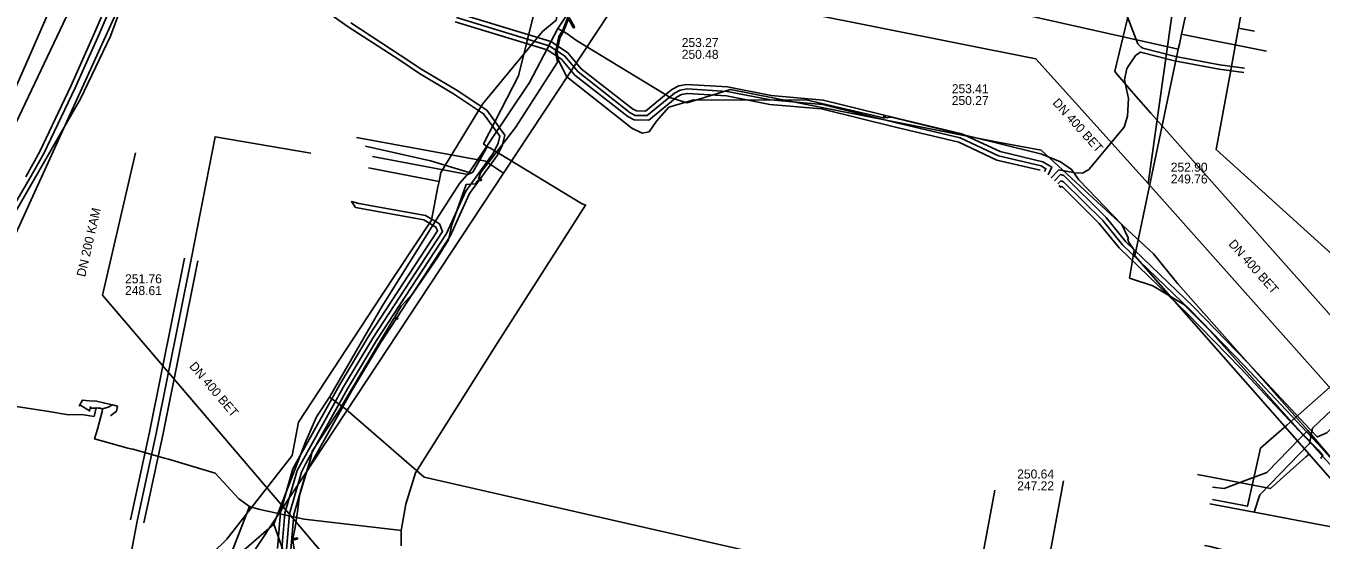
# Model space of a CAD drawing. Extents: x -598233 to -596890, y -1157848 to -1156431.
# Drawn here: x -597184.3 to -597069.1, y -1157535.5 to -1157489.7 of the extents above; entities that cross this region are included whole.
import ezdxf

# ---------------------------------------------------------------- set-up
doc = ezdxf.new("R2010")
doc.units = 0
for name, color, linetype in [('Vrstva 12', 7, 'Continuous'), ('Vrstva 13', 7, 'Continuous'), ('Vrstva 16', 7, 'Continuous'), ('Vrstva 19', 7, 'Continuous'), ('Vrstva 37', 7, 'Continuous'), ('Vrstva 38', 7, 'Continuous'), ('Vrstva 42', 7, 'Continuous'), ('Vrstva 48', 7, 'Continuous'), ('Vrstva 51', 7, 'Continuous'), ('Vrstva 55', 7, 'Continuous'), ('Vrstva 58', 7, 'Continuous'), ('Vrstva 9', 7, 'Continuous')]:
    doc.layers.add(name, color=color, linetype=linetype)

msp = doc.modelspace()

# ---------------------------------------------------------------- linework, layer by layer
at = {"layer": 'Vrstva 12'}
for points in [[(-597138.34, -1157490.22), (-597137.14, -1157489.22), (-597136.59, -1157486.27), (-597125.79, -1157469.77), (-597124.28, -1157461.93), (-597123.72, -1157458.99), (-597123.41, -1157457.42)], [(-597174.83, -1157472), (-597177.82, -1157478.71), (-597180.61, -1157484.62), (-597183.79, -1157492), (-597187.73, -1157500.85), (-597191.49, -1157508.74), (-597195.12, -1157516.56)], [(-597076.44, -1157489.91), (-597076.05, -1157487.75), (-597077.34, -1157487.41)], [(-597140.9, -1157493.31), (-597138.34, -1157490.22)], [(-597054.42, -1157516.11), (-597061.64, -1157514.31), (-597064.06, -1157513.71), (-597078.43, -1157500.72), (-597077.19, -1157493.99), (-597076.47, -1157490.05), (-597076.44, -1157489.91)], [(-597076.44, -1157489.91), (-597075.01, -1157490.19)], [(-597147.55, -1157503.56), (-597147.39, -1157502.77), (-597143.68, -1157496.67), (-597140.9, -1157493.31)], [(-597153.84, -1157502.35), (-597147.55, -1157503.56)], [(-597167.72, -1157536.67), (-597166.44, -1157535.4), (-597160.63, -1157527.93), (-597160.06, -1157524.98), (-597152.69, -1157513.78), (-597148.22, -1157507), (-597147.65, -1157504.05), (-597147.55, -1157503.56)], [(-597074.55, -1157531.45), (-597070.12, -1157526.89), (-597069.86, -1157525.52), (-597063.07, -1157519.07), (-597053.69, -1157520.64)], [(-597075.04, -1157532.98), (-597074.55, -1157531.45)], [(-597078.98, -1157532.23), (-597075.04, -1157532.98)], [(-597052.3, -1157558.29), (-597051.14, -1157552.4), (-597050.78, -1157550.53), (-597059.55, -1157540.67), (-597063.92, -1157539.81), (-597063.78, -1157539.1), (-597063.22, -1157536.13), (-597063.05, -1157535.26), (-597075.04, -1157532.98)]]:
    msp.add_lwpolyline(points, dxfattribs=at)
at = {"layer": 'Vrstva 13'}
for p, q in [((-597187.26, -1157502.69), (-597170.45, -1157467.35)), ((-597081.79, -1157491.79), (-597081.7, -1157491.34)), ((-597082.19, -1157491.7), (-597081.79, -1157491.79)), ((-597081.85, -1157492.09), (-597081.79, -1157491.79))]:
    msp.add_line(p, q, dxfattribs=at)
for points in [[(-597026.92, -1157402.38), (-597036.5, -1157429.51), (-597036.81, -1157430.39), (-597055.35, -1157434.11), (-597061.26, -1157454.58), (-597076.71, -1157468.49), (-597081.5, -1157490.45), (-597081.7, -1157491.34)], [(-597082.19, -1157491.7), (-597108.02, -1157485.89), (-597126.01, -1157481.84), (-597126.61, -1157481.7), (-597127.71, -1157481.44), (-597141.82, -1157502.82), (-597164.3, -1157536.89), (-597164.29, -1157537.06), (-597161.57, -1157540.12), (-597158.67, -1157543.36), (-597141.32, -1157562.83), (-597138.68, -1157565.79), (-597117.79, -1157589.22), (-597114.74, -1157592.65), (-597094.8, -1157615.01), (-597091.36, -1157618.87), (-597086.95, -1157623.82), (-597081.9, -1157629.49), (-597080.86, -1157631.56)], [(-597081.5, -1157490.45), (-597081.25, -1157490.51), (-597073.95, -1157491.98)], [(-597010.06, -1157596.34), (-597010.19, -1157596.08), (-597019.57, -1157585.41), (-597022.72, -1157581.82), (-597034.39, -1157568.53), (-597043.31, -1157558.37), (-597046.79, -1157554.42), (-597066.65, -1157531.82), (-597070.16, -1157527.82), (-597081.02, -1157515.45), (-597085.67, -1157510.17), (-597081.85, -1157492.09)], [(-597141.82, -1157502.82), (-597142.26, -1157502.53), (-597143.41, -1157501.75), (-597154.9, -1157499.65)], [(-597070.16, -1157527.82), (-597070.44, -1157528.07), (-597073.59, -1157530.89), (-597080.09, -1157529.62)]]:
    msp.add_lwpolyline(points, dxfattribs=at)
at = {"layer": 'Vrstva 16'}
for points in [[(-597180.5, -1157524.34), (-597182.25, -1157524.03), (-597191.3, -1157522.62)], [(-597178.98, -1157524.36), (-597179.36, -1157524.3), (-597180.5, -1157524.34)], [(-597178.61, -1157524.42), (-597178.98, -1157524.36)], [(-597177.48, -1157523.8), (-597178.06, -1157523.69), (-597178.06, -1157523.7), (-597178.23, -1157524.47), (-597178.61, -1157524.42)]]:
    msp.add_lwpolyline(points, dxfattribs=at)
at = {"layer": 'Vrstva 19'}
for points in [[(-597065.1, -1157519.01), (-597084.25, -1157497.49), (-597085.78, -1157495.74), (-597087.36, -1157493.91), (-597087.44, -1157493.75), (-597085.94, -1157487.46)], [(-597138.99, -1157488.18), (-597140.48, -1157494.15), (-597143.59, -1157500.22), (-597143.27, -1157500.47), (-597143.03, -1157500.58), (-597134.88, -1157505.53), (-597134.52, -1157505.66), (-597142.35, -1157517.93), (-597149.65, -1157529.49), (-597150.51, -1157532.26), (-597150.93, -1157534.62), (-597150.91, -1157535.99)], [(-597143.27, -1157500.47), (-597144.54, -1157502.74), (-597144.99, -1157502.94), (-597153.48, -1157501.33)], [(-597065.1, -1157519.01), (-597065.32, -1157519.21), (-597072.13, -1157525.25), (-597074.47, -1157527.29), (-597075.65, -1157532.46), (-597078.75, -1157531.87)], [(-597175.22, -1157527.28), (-597178.19, -1157526.47), (-597177.93, -1157525.61), (-597177.53, -1157524.02)], [(-597177.53, -1157524.02), (-597177.48, -1157523.81), (-597177.48, -1157523.8)], [(-597171.62, -1157528.27), (-597171.97, -1157528.17), (-597174.8, -1157527.39), (-597174.98, -1157527.35), (-597175.22, -1157527.28)], [(-597150.93, -1157534.62), (-597151.13, -1157534.6), (-597159.56, -1157533.62), (-597163.62, -1157532.73), (-597164.42, -1157532.47), (-597165.37, -1157531.79), (-597167.48, -1157529.52), (-597171.62, -1157528.27)], [(-597164.42, -1157532.47), (-597167.64, -1157540.78), (-597168.21, -1157541.47), (-597169.13, -1157541.58), (-597173.47, -1157540.61)]]:
    msp.add_lwpolyline(points, dxfattribs=at)
at = {"layer": 'Vrstva 37'}
for points in [[(-597169.61, -1157510.5), (-597167.47, -1157499.58), (-597158.97, -1157501.05)], [(-597174.4, -1157533.8), (-597172.71, -1157526), (-597169.61, -1157510.5)], [(-597174.4, -1157533.8), (-597172.71, -1157526), (-597169.61, -1157510.5)], [(-597080.84, -1157542.09), (-597093.7, -1157539.3), (-597092.01, -1157530.19)], [(-597175.7, -1157550.96), (-597177.54, -1157550.44), (-597174.4, -1157533.8)]]:
    msp.add_lwpolyline(points, dxfattribs=at)
at = {"layer": 'Vrstva 38'}
for points in [[(-597174.99, -1157533.67), (-597173.3, -1157525.88), (-597170.2, -1157510.38)], [(-597173.82, -1157533.93), (-597172.12, -1157526.13), (-597169.02, -1157510.61)]]:
    msp.add_lwpolyline(points, dxfattribs=at)
at = {"layer": 'Vrstva 42'}
for points in [[(-597075.9, -1157493.47), (-597078.1, -1157493.18), (-597082.03, -1157492.44), (-597084.96, -1157491.69), (-597085.12, -1157491.58), (-597085.4, -1157491.33), (-597086.74, -1157487.85), (-597087.83, -1157485.44), (-597089.6, -1157483.06), (-597090.83, -1157481.21), (-597092.97, -1157478.52), (-597094.33, -1157477.55), (-597094.92, -1157477.28), (-597100.87, -1157476.16), (-597101.47, -1157475.86), (-597101.92, -1157475.33), (-597102, -1157474.66), (-597101.59, -1157471.8), (-597100.58, -1157467.66), (-597100.41, -1157467.46), (-597100.25, -1157467.42), (-597099.1, -1157467.34)], [(-597184.32, -1157503.14), (-597183.06, -1157500.9), (-597180.29, -1157495.08), (-597178.16, -1157490.29), (-597176.06, -1157485.39), (-597175.44, -1157484.62), (-597174.5, -1157482.84), (-597173.45, -1157481.76), (-597172.48, -1157481.55), (-597172.44, -1157481.51), (-597172.32, -1157481.38), (-597172.32, -1157481.34), (-597172.29, -1157481.22), (-597172.25, -1157481.04), (-597172.01, -1157480.58), (-597171.8, -1157480.17), (-597171.51, -1157479.62), (-597170.57, -1157477.79), (-597168.92, -1157473.93), (-597167.58, -1157470.87), (-597166.63, -1157470.7), (-597164.29, -1157470.3)], [(-597175.72, -1157485.59), (-597177.79, -1157490.45), (-597179.93, -1157495.24), (-597182.7, -1157501.08), (-597183.98, -1157503.34), (-597185.69, -1157506.27)], [(-597161.07, -1157538.33), (-597161.02, -1157538.28), (-597161.24, -1157537.24), (-597161.13, -1157536.31), (-597160.86, -1157533.13), (-597159.8, -1157529.44), (-597159.39, -1157528.67), (-597155.7, -1157522.02), (-597153.11, -1157517.72), (-597146.88, -1157508.2), (-597145.18, -1157504.42), (-597142.71, -1157501.01), (-597142.29, -1157500.16), (-597142.13, -1157499.52), (-597143.59, -1157497.53), (-597146.26, -1157495.76), (-597149.29, -1157493.95), (-597151.14, -1157492.71), (-597155.64, -1157489.79), (-597161.37, -1157485.75)], [(-597146.01, -1157488.97), (-597137.77, -1157491.49), (-597136.39, -1157492.39), (-597135.19, -1157493.82), (-597130.55, -1157497.45), (-597130.1, -1157497.68), (-597129.04, -1157497.7), (-597126.6, -1157495.71), (-597126.1, -1157495.44), (-597125.48, -1157495.33), (-597121.93, -1157495.55), (-597118.08, -1157496.3), (-597113.45, -1157496.72), (-597106.85, -1157498.34), (-597101.19, -1157499.69), (-597097.78, -1157501.28), (-597093.99, -1157502.18), (-597093.57, -1157502.43), (-597093.68, -1157502.67)], [(-597145.9, -1157488.59), (-597137.6, -1157491.12), (-597136.12, -1157492.09), (-597134.91, -1157493.53), (-597130.34, -1157497.11), (-597130, -1157497.28), (-597129.18, -1157497.3), (-597126.83, -1157495.37), (-597126.23, -1157495.05), (-597125.5, -1157494.93), (-597121.88, -1157495.15), (-597118.02, -1157495.91), (-597113.38, -1157496.32), (-597106.75, -1157497.95), (-597101.06, -1157499.31), (-597097.65, -1157500.9), (-597093.83, -1157501.81), (-597093.05, -1157502.28), (-597093.38, -1157502.96)], [(-597155.41, -1157489.46), (-597150.92, -1157492.38), (-597149.07, -1157493.61), (-597146.04, -1157495.42), (-597143.31, -1157497.23), (-597141.69, -1157499.44), (-597141.92, -1157500.3), (-597142.36, -1157501.21), (-597144.84, -1157504.63), (-597146.55, -1157508.42), (-597152.77, -1157517.93), (-597155.35, -1157522.22), (-597159.04, -1157528.86), (-597159.43, -1157529.59), (-597160.47, -1157533.2), (-597160.73, -1157536.34), (-597160.83, -1157537.22), (-597160.63, -1157538.18), (-597160.96, -1157538.45)], [(-597146.13, -1157489.36), (-597137.94, -1157491.85), (-597136.66, -1157492.69), (-597135.47, -1157494.11), (-597130.77, -1157497.79), (-597130.2, -1157498.07), (-597128.9, -1157498.1), (-597126.38, -1157496.04), (-597125.97, -1157495.82), (-597125.46, -1157495.73), (-597121.98, -1157495.95), (-597118.13, -1157496.7), (-597113.52, -1157497.11), (-597106.94, -1157498.73), (-597101.32, -1157500.07), (-597097.92, -1157501.66), (-597094.09, -1157502.57)], [(-597075.97, -1157493.86), (-597078.16, -1157493.58), (-597082.12, -1157492.83), (-597085.15, -1157492.05), (-597085.57, -1157492.32), (-597086.02, -1157492.97), (-597086.37, -1157493.51), (-597086.57, -1157494.52), (-597086.23, -1157496.17), (-597086.3, -1157497.76), (-597086.62, -1157498.73), (-597089.76, -1157502.49), (-597090.3, -1157502.81), (-597091, -1157502.8), (-597092.43, -1157502.54), (-597093.09, -1157503.24)], [(-597169.61, -1157510.5), (-597167.47, -1157499.58), (-597158.97, -1157501.05)], [(-597092.81, -1157503.51), (-597092.28, -1157502.95), (-597091.97, -1157503.04), (-597088.22, -1157506.77), (-597086.47, -1157508.93), (-597080.43, -1157514.73), (-597075.65, -1157519.66), (-597070.05, -1157525.64), (-597069.43, -1157526.28), (-597069.42, -1157526.27), (-597068.58, -1157525.94), (-597065.97, -1157523.31), (-597063.23, -1157519.67), (-597063.11, -1157519.59), (-597061.99, -1157519.05), (-597061.24, -1157518.5), (-597060.06, -1157518.59), (-597055.56, -1157519.31), (-597051.82, -1157519.78), (-597051.83, -1157519.88)], [(-597092.52, -1157503.78), (-597092.25, -1157503.51), (-597091.99, -1157503.58), (-597088.52, -1157507.04), (-597086.76, -1157509.2), (-597080.71, -1157515.02), (-597075.94, -1157519.93), (-597070.34, -1157525.91), (-597069.38, -1157526.9), (-597069.33, -1157526.96), (-597065.28, -1157531.47)], [(-597092.42, -1157503.92), (-597092.25, -1157504.08), (-597092.19, -1157504.02), (-597092.09, -1157504.05), (-597088.82, -1157507.31), (-597087.06, -1157509.47), (-597080.99, -1157515.3), (-597076.23, -1157520.21), (-597070.63, -1157526.19), (-597069.72, -1157527.13), (-597069.7, -1157527.16), (-597065.58, -1157531.74), (-597059.49, -1157538.54), (-597057.65, -1157540.65), (-597057.61, -1157540.79), (-597057.81, -1157541.11), (-597057.96, -1157541.17), (-597062.88, -1157539.95), (-597069, -1157538.52), (-597076.17, -1157536.79), (-597078.97, -1157536.05), (-597079.45, -1157535.96)], [(-597161.93, -1157536.23), (-597161.65, -1157532.98), (-597160.55, -1157529.13), (-597160.09, -1157528.28), (-597156.39, -1157521.62), (-597153.79, -1157517.3), (-597147.68, -1157507.96), (-597147.83, -1157507.62), (-597148.91, -1157506.98), (-597154.97, -1157505.87), (-597155.33, -1157505.35), (-597154.7, -1157505.52), (-597148.76, -1157506.6), (-597147.52, -1157507.34), (-597147.23, -1157508), (-597153.45, -1157517.51), (-597156.04, -1157521.82), (-597159.74, -1157528.48), (-597160.18, -1157529.29), (-597161.26, -1157533.06), (-597161.53, -1157536.27)], [(-597174.4, -1157533.8), (-597172.71, -1157526), (-597169.61, -1157510.5)], [(-597080.84, -1157542.09), (-597093.7, -1157539.3), (-597092.01, -1157530.19)], [(-597175.7, -1157550.96), (-597177.54, -1157550.44), (-597174.4, -1157533.8)]]:
    msp.add_lwpolyline(points, dxfattribs=at)
at = {"layer": 'Vrstva 48'}
for points in [[(-597176.78, -1157524.4), (-597176.25, -1157524), (-597176.16, -1157523.56), (-597176.61, -1157523.45), (-597177.28, -1157523.29), (-597178.01, -1157523.12), (-597178.67, -1157523.07), (-597179.28, -1157523.01), (-597179.5, -1157523.43), (-597179.57, -1157523.54)], [(-597179.5, -1157523.43), (-597178.63, -1157523.98), (-597178.58, -1157523.73), (-597178.56, -1157523.58)], [(-597176.61, -1157523.45), (-597176.99, -1157523.64), (-597177.48, -1157523.8), (-597177.8, -1157523.69), (-597178.02, -1157523.74), (-597178.58, -1157523.73)]]:
    msp.add_lwpolyline(points, dxfattribs=at)
at = {"layer": 'Vrstva 51'}
msp.add_lwpolyline([(-597162.16, -1157462.41), (-597162.37, -1157462.79), (-597162.45, -1157462.93), (-597162.55, -1157463.11), (-597162.62, -1157463.25), (-597162.74, -1157463.48), (-597162.94, -1157463.85), (-597163.14, -1157464.22), (-597163.47, -1157464.84), (-597163.79, -1157465.42), (-597165.74, -1157469.04), (-597165.98, -1157469.49), (-597166.19, -1157469.89), (-597166.4, -1157470.28), (-597166.63, -1157470.7), (-597171.49, -1157479.73), (-597171.77, -1157480.25), (-597171.97, -1157480.63), (-597172.29, -1157481.22), (-597172.34, -1157481.32), (-597172.44, -1157481.51), (-597172.71, -1157482.01), (-597176.29, -1157488.66), (-597185.93, -1157509.83)], dxfattribs=at)
at = {"layer": 'Vrstva 55'}
for points in [[(-597158.82, -1157477.15), (-597161.21, -1157476.69), (-597167.17, -1157475.31), (-597170.24, -1157474.33), (-597170.61, -1157474.61), (-597170.79, -1157475.8), (-597170.6, -1157477.17), (-597172.39, -1157481.32), (-597172.9, -1157482.22), (-597174.85, -1157485.44), (-597174.81, -1157485.58), (-597174.95, -1157485.61), (-597176.78, -1157490.63), (-597179.45, -1157496.2), (-597186.75, -1157508.85), (-597186.82, -1157508.91), (-597186.81, -1157508.98), (-597188.5, -1157512.52), (-597188.32, -1157512.99), (-597187.84, -1157513.32), (-597187.8, -1157513.39)], [(-597135.85, -1157488.35), (-597136.58, -1157490.15), (-597136.9, -1157490.67), (-597137.19, -1157492.05), (-597137.01, -1157492.94), (-597140.74, -1157498.77), (-597143.87, -1157502.79), (-597144.04, -1157503.35), (-597143.79, -1157503.37), (-597143.75, -1157503.43), (-597143.81, -1157503.49), (-597144.1, -1157503.47), (-597144.3, -1157503.76), (-597145.13, -1157503.83), (-597146.41, -1157507.43), (-597146.71, -1157508.76), (-597147.62, -1157510.24), (-597149.87, -1157513.54), (-597150.92, -1157514.67), (-597151.47, -1157515.6), (-597151.25, -1157515.69), (-597151.23, -1157515.77), (-597151.3, -1157515.8), (-597151.53, -1157515.7), (-597152.63, -1157517.54), (-597156.47, -1157523.98), (-597158.85, -1157527.57), (-597158.95, -1157528.16), (-597159.97, -1157531.49), (-597160.12, -1157532.71), (-597160.36, -1157534.34), (-597160.56, -1157535.35), (-597160.19, -1157535.27), (-597160.12, -1157535.32), (-597160.17, -1157535.39), (-597160.56, -1157535.47), (-597160.08, -1157538.81)], [(-597069.09, -1157528.2), (-597069.09, -1157528.11), (-597068.95, -1157527.95), (-597069.35, -1157527.45), (-597070.91, -1157525.84), (-597078.99, -1157516.83), (-597081.31, -1157514.5), (-597084.06, -1157512.85), (-597086.12, -1157512.16), (-597085.73, -1157509.67), (-597086.23, -1157508.92), (-597086.24, -1157508.79), (-597086.29, -1157508.73), (-597086.24, -1157508.67), (-597086.25, -1157508.57), (-597086.83, -1157507.4), (-597090.64, -1157503.42), (-597091.29, -1157502.49), (-597092.28, -1157501.82), (-597093.93, -1157501.12), (-597098.11, -1157500.1), (-597107.31, -1157497.83), (-597107.91, -1157497.9), (-597107.88, -1157497.76), (-597107.93, -1157497.69), (-597108, -1157497.74), (-597108.03, -1157497.9), (-597114.77, -1157496.33), (-597124.9, -1157496.3), (-597127.11, -1157496.96), (-597128.21, -1157498.19), (-597128.87, -1157499.14), (-597129.49, -1157499.27), (-597130.39, -1157498.81), (-597136.17, -1157494.26), (-597136.9, -1157492.86), (-597137.07, -1157492.05), (-597136.78, -1157490.71), (-597136.48, -1157490.21), (-597136.03, -1157489.1), (-597135.61, -1157489.86), (-597135.52, -1157489.9), (-597135.51, -1157489.8), (-597135.97, -1157488.96)]]:
    msp.add_lwpolyline(points, dxfattribs=at)
at = {"layer": 'Vrstva 58'}
for points in [[(-597120.35, -1157456.05), (-597120.83, -1157457.84), (-597120.99, -1157458.55), (-597121.21, -1157459.32), (-597122.25, -1157463.07), (-597125.24, -1157470.21), (-597132.81, -1157479.65), (-597135.11, -1157485.05), (-597135.84, -1157488.1), (-597136.26, -1157488.87), (-597136.97, -1157489.96)], [(-597136.97, -1157489.96), (-597139.5, -1157494.77), (-597144.87, -1157502.76)], [(-597136.97, -1157489.96), (-597136.18, -1157490.39), (-597135.33, -1157491.03), (-597126.94, -1157496.13), (-597125.48, -1157496.57), (-597121.63, -1157495.38), (-597097.85, -1157500.06), (-597093.98, -1157500.77), (-597083.99, -1157509.99), (-597081.84, -1157512.66), (-597070.28, -1157525.71)], [(-597144.87, -1157502.76), (-597148.3, -1157501.74), (-597154.1, -1157500.43)], [(-597144.87, -1157502.76), (-597145.73, -1157503.75), (-597147.74, -1157506.9), (-597152.61, -1157514.66), (-597157.29, -1157522.75)], [(-597157.29, -1157522.75), (-597158.46, -1157524.49), (-597159.47, -1157526.83), (-597162.25, -1157534.04)], [(-597157.29, -1157522.75), (-597155.84, -1157523.82), (-597148.88, -1157529.87), (-597120.4, -1157536.38)], [(-597070.28, -1157525.71), (-597070.95, -1157526.41), (-597073.91, -1157529.45), (-597075.75, -1157530.13), (-597077.72, -1157530.88), (-597078.76, -1157530.75)], [(-597070.28, -1157525.71), (-597061.54, -1157535.99), (-597057.18, -1157540.66), (-597047.03, -1157552.41)], [(-597162.25, -1157534.04), (-597169.12, -1157540.02), (-597170.22, -1157540.62), (-597173.59, -1157540.08)], [(-597162.25, -1157534.04), (-597160.96, -1157537.68), (-597159.14, -1157543.39), (-597157.88, -1157544.91), (-597155.19, -1157548.82), (-597154.5, -1157550.15), (-597153.24, -1157550.23), (-597141.71, -1157562.3)]]:
    msp.add_lwpolyline(points, dxfattribs=at)
at = {"layer": 'Vrstva 9'}
for p, q in [((-597079.86, -1157470.87), (-597084.46, -1157503.74)), ((-597122.95, -1157486.96), (-597094.48, -1157492.65)), ((-597174.56, -1157501), (-597177.48, -1157513.67)), ((-597084.46, -1157503.74), (-597061.21, -1157529.91))]:
    msp.add_line(p, q, dxfattribs=at)
for points in [[(-597094.48, -1157492.65), (-597089.3, -1157498.38), (-597084.46, -1157503.74)], [(-597177.48, -1157513.67), (-597160.23, -1157533.91), (-597157.46, -1157537.16), (-597152.03, -1157543.53)], [(-597098.12, -1157531.04), (-597101.05, -1157546.82), (-597102.98, -1157557.24)]]:
    msp.add_lwpolyline(points, dxfattribs=at)

# ---------------------------------------------------------------- texts
at = {"layer": 'Vrstva 12'}
for s, p in [('253.27', (-597125.96, -1157491.6)), ('250.48', (-597125.96, -1157492.65)), ('253.41', (-597101.94, -1157495.71)), ('250.27', (-597101.94, -1157496.76)), ('252.90', (-597082.46, -1157502.69)), ('249.76', (-597082.46, -1157503.74)), ('251.76', (-597175.48, -1157512.62)), ('248.61', (-597175.48, -1157513.67)), ('250.64', (-597096.12, -1157529.99)), ('247.22', (-597096.12, -1157531.04))]:
    msp.add_text(s, height=0.8, dxfattribs=at).set_placement(p)
for s, rotation, p in [('DN 400 BET', 312.0901, (-597093.03, -1157496.61)), ('DN 200 KAM', 77.0628, (-597179.03, -1157512.1)), ('DN 400 BET', 311.6317, (-597077.38, -1157509.16)), ('DN 400 BET', 310.4285, (-597169.82, -1157520.03))]:
    msp.add_text(s, height=0.8, rotation=rotation, dxfattribs=at).set_placement(p)

doc.saveas('drawing.dxf')
